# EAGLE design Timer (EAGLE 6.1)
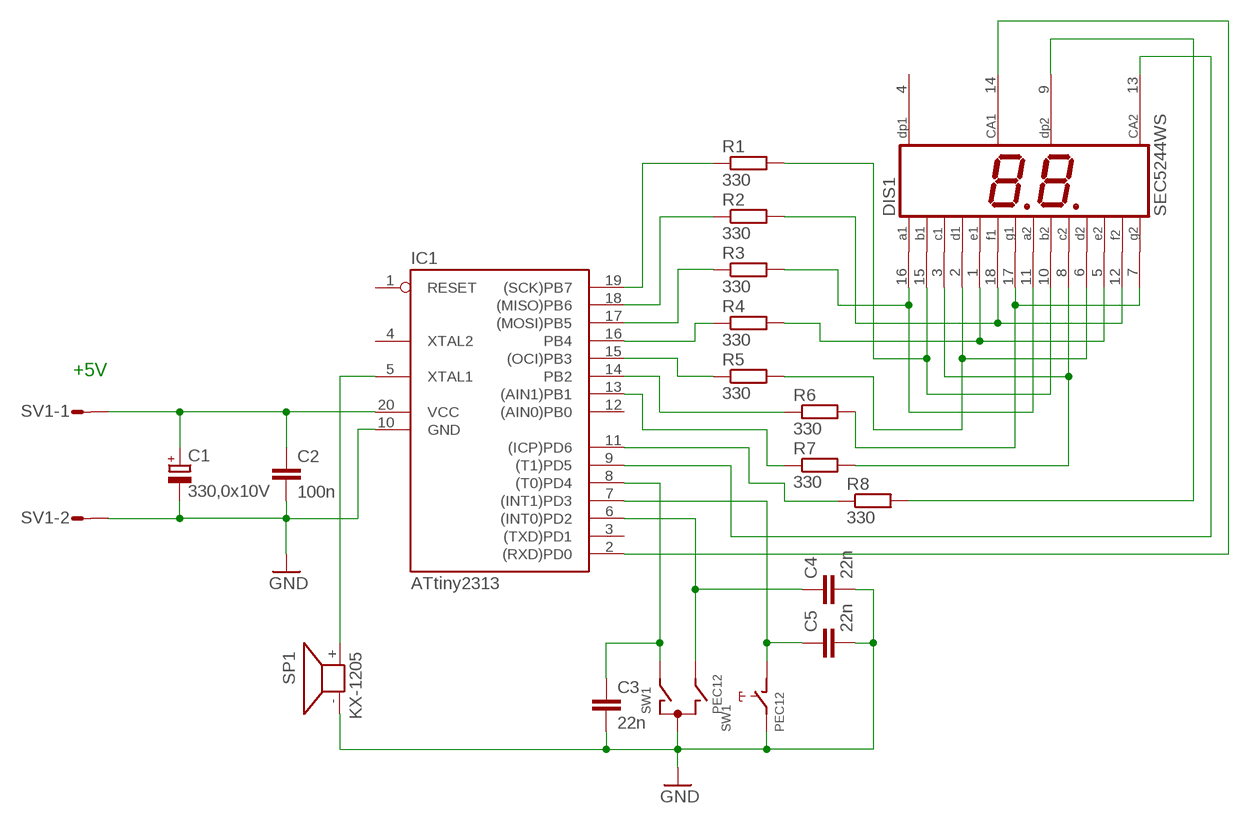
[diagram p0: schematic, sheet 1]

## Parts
C1  330,0x10V  CPOL-EU085CS-1AR  [085CS_1AR]
C2  100n  C-EUC1206  [C1206]
C3  22n  C-EUC1206  [C1206]
C4  22n  C-EUC1206  [C1206]
C5  22n  C-EUC1206  [C1206]
DIS1  SEC5244WS  HD-K121  [HDSP-R]
IC1  ATtiny2313  AT90S2313P  [DIL20]
R1  330  R-EU_R1206  [R1206]
R2  330  R-EU_R1206  [R1206]
R3  330  R-EU_R1206  [R1206]
R4  330  R-EU_R1206  [R1206]
R5  330  R-EU_R1206  [R1206]
R6  330  R-EU_R1206  [R1206]
R7  330  R-EU_R1206  [R1206]
R8  330  R-EU_R1206  [R1206]
SP1  KX-1205  KSS1201  [KSS1201]
SV1  S02P  [S02P]
SW1  PEC12  EC12E_SW  [ALPS_EC12E_SW]

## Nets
GND: C1.- C2.2 C3.2 C4.2 C5.2 IC1.10(GND) SP1.- SV1.2 SW1.C SW1.E
N$1: C1.+ C2.1 IC1.20(VCC) SV1.1
N$2: IC1.14(PB2) R6.1
N$3: IC1.15((OCI)PB3) R5.1
N$4: IC1.16(PB4) R4.1
N$5: IC1.17((MOSI)PB5) R3.1
N$6: IC1.18((MISO)PB6) R2.1
N$7: IC1.19((SCK)PB7) R1.1
N$8: IC1.13((AIN1)PB1) R7.1
N$9: IC1.11((ICP)PD6) R8.1
N$11: DIS1.13(CA2) IC1.9((T1)PD5)
N$12: DIS1.10(B2) DIS1.15(B1) R1.2
N$13: DIS1.9(DP2) R8.2
N$14: DIS1.3(C1) DIS1.8(C2) R7.2
N$15: DIS1.2(D1) DIS1.6(D2) R5.2
N$16: DIS1.14(CA1) IC1.2((RXD)PD0)
N$17: DIS1.12(F2) DIS1.18(F1) R2.2
N$18: DIS1.7(G2) DIS1.17(G1) R6.2
N$19: IC1.5(XTAL1) SP1.+
N$20: DIS1.11(A2) DIS1.16(A1) R3.2
N$21: DIS1.1(E1) DIS1.5(E2) R4.2
N$26: C5.1 IC1.7((INT1)PD3) SW1.D
N$28: C3.1 IC1.8((T0)PD4) SW1.A
N$29: C4.1 IC1.6((INT0)PD2) SW1.B
Unconnected: DIS1.4(DP1) IC1.1(RESET) IC1.3((TXD)PD1) IC1.4(XTAL2) IC1.12((AIN0)PB0) SW1.GND1(G) SW1.GND2(G)

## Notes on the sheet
- +5V

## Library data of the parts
C1 = resistor:CPOL-EU: POLARIZED CAPACITOR, European symbol
C2-C5 = resistor:C-EU: CAPACITOR, European symbol
DIS1 = display-hp:HD-K121: LED DISPLAY 2 x 1 character 7 segment, decimal points right; OC_FARNELL: unknown; OC_NEWARK: unknown
IC1 = atmel:AT90S2313: MICROCONTROLLER 2 Kbytes FLASH 128 bytes SRAM 128 bytes EEPROM UART; OC_FARNELL: unknown; OC_NEWARK: unknown
R1-R8 = resistor:R-EU_: RESISTOR, European symbol
SP1 = buzzer:KSS1201: SPEAKER; OC_FARNELL: unknown; OC_NEWARK: unknown
SV1 = con-amp-mt:S02P: AMP MT CONNECTOR; OC_FARNELL: unknown; OC_NEWARK: unknown
SW1 = switch-alps:EC12E_SW: ALPS rotary Encoder EC12E series with switch; MPN: EC12E2424407; OC_FARNELL: 1520813; OC_NEWARK: 74M1068

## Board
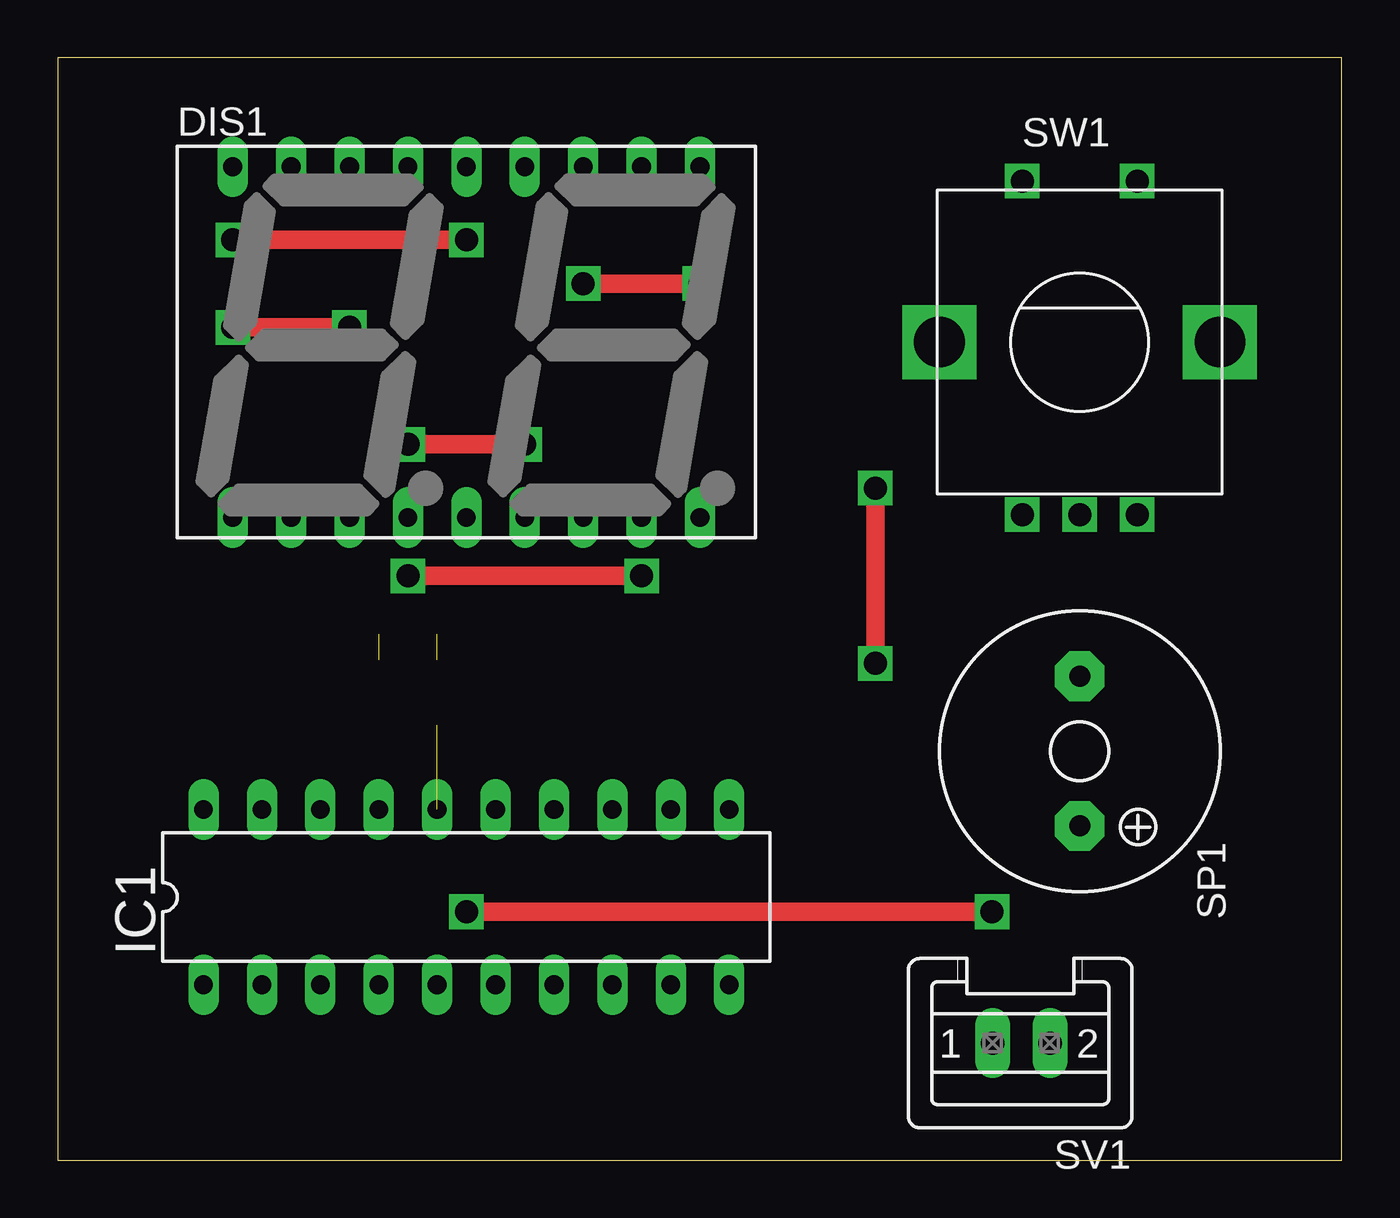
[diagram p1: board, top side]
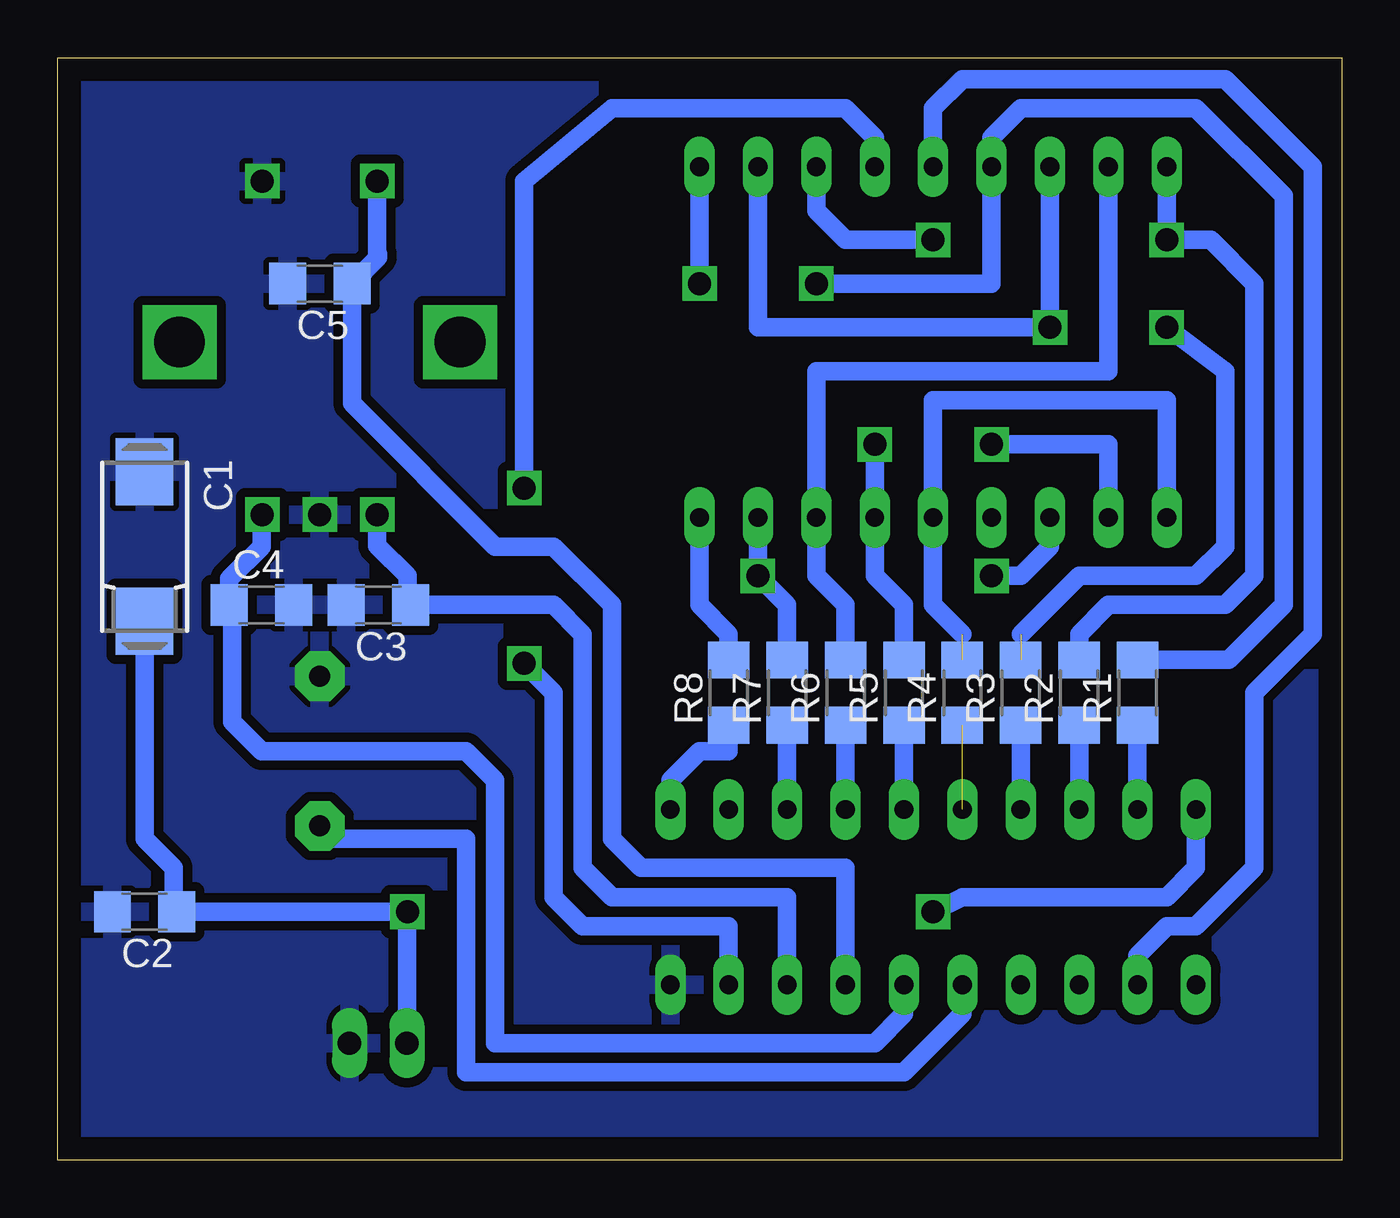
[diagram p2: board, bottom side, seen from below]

Size 55.86 x 47.93 mm. Coordinates in mm from the lower left corner, seen from the top.
Outline: 0,0 55.86,0 55.86,47.93 0,47.93 0,0
Copper layers (1*16): Top 0.035mm / dielectric 1.5mm / Bottom 0.035mm
Design rules "default": minimum track width 10mil, minimum drill 24mil, track to track 8mil, track to pad 8mil, pad to pad 8mil, via to via 8mil, smd to smd 8mil, copper to edge 40mil, drill to drill 8mil, minimum pad ring 10mil, minimum via ring 8mil, stop-mask expansion 4mil, vias tented up to drill 0mil, thermal gap 10mil

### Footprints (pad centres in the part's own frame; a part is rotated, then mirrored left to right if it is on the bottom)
085CS_1AR = smd 2.9 x 2.5: + 3.25,0; - -3.25,0
C1206 = smd 1.6 x 1.8: 1 -1.4,0; 2 1.4,0
HDSP-R = drill 0.813 long: 1 -10.16,-7.62; 2 -7.62,-7.62; 3 -5.08,-7.62; 4 -2.54,-7.62; 5 0,-7.62; 6 2.54,-7.62; 7 5.08,-7.62; 8 7.62,-7.62; 9 10.16,-7.62; 10 10.16,7.62; 11 7.62,7.62; 12 5.08,7.62; 13 2.54,7.62; 14 0,7.62; 15 -2.54,7.62; 16 -5.08,7.62; 17 -7.62,7.62; 18 -10.16,7.62
DIL20 = drill 0.813 long: 1 -11.43,-3.81; 2 -8.89,-3.81; 3 -6.35,-3.81; 4 -3.81,-3.81; 5 -1.27,-3.81; 6 1.27,-3.81; 7 3.81,-3.81; 8 6.35,-3.81; 9 8.89,-3.81; 10 11.43,-3.81; 11 11.43,3.81; 12 8.89,3.81; 13 6.35,3.81; 14 3.81,3.81; 15 1.27,3.81; 16 -1.27,3.81; 17 -3.81,3.81; 18 -6.35,3.81; 19 -8.89,3.81; 20 -11.43,3.81
R1206 = smd 1.6 x 1.803: 1 -1.422,0; 2 1.422,0
KSS1201 = drill 0.914 pad 2.159 octagon: + 3.251,0; - -3.251,0
S02P = drill 1.016 long: 1 1.25,0; 2 -1.25,0
ALPS_EC12E_SW = drill 1 square: A -2.5,-7.5; B 2.5,-7.5; C 0,-7.5; D -2.5,7; E 2.5,7 | drill 2.2 square: GND1 -6.1,0; GND2 6.1,0

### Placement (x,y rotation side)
C1  52.07,26.67 270 bottom
C2  52.07,10.79 180 bottom
C3  41.91,24.13 180 bottom
C4  46.99,24.13 0 bottom
C5  44.45,38.1 180 bottom
DIS1  17.78,35.56 0 top
IC1  17.78,11.43 0 top
R1  8.89,20.32 90 bottom
R2  11.43,20.32 90 bottom
R3  13.97,20.32 90 bottom
R4  16.51,20.32 90 bottom
R5  19.05,20.32 90 bottom
R6  21.59,20.32 90 bottom
R7  24.13,20.32 90 bottom
R8  26.67,20.32 90 bottom
SP1  44.45,17.78 270 top
SV1  41.91,5.08 180 top
SW1  44.45,35.56 0 top

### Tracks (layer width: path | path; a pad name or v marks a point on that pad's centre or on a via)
GND
  Bottom 0.813: SW1.C 44.45,27.94
  pour Bottom (isolate 0.406): 0,48.26 55.88,48.26 55.88,0 0,0
N$1  (via drill 1)
  Top 0.813: v17.78,10.79 v40.64,10.79
  Bottom 0.813: IC1.20 6.35,12.7 7.62,11.43 16.51,11.43 v17.78,10.79 | SV1.1 40.66,10.14 v40.64,10.79 C2.1 50.8,11.56 50.8,12.7 52.07,13.97 C1.+
N$2
  Bottom 0.813: IC1.14 R6.1
N$3
  Bottom 0.813: IC1.15 R5.1
N$4  (1 unrouted)
N$5
  Bottom 0.813: IC1.17 R3.1
N$6
  Bottom 0.813: IC1.18 R2.1 IC1.18
N$7
  Bottom 0.813: IC1.19 R1.1
N$8
  Bottom 0.813: IC1.13 R7.1
N$9
  Bottom 0.813: R8.1 26.67,17.78 27.94,17.78 29.21,16.51 IC1.11
N$11  (via drill 1)
  Top 0.813: v35.56,21.59 v35.56,29.21
  Bottom 0.813: IC1.9 26.67,10.16 33.02,10.16 34.29,11.43 34.29,20.32 v35.56,21.59 | DIS1.13 20.32,44.45 21.59,45.72 31.75,45.72 35.56,42.55 v35.56,29.21
N$12  (via drill 1)
  Top 0.813: v22.86,38.1 v27.94,38.1
  Bottom 0.813: v27.94,38.1 DIS1.10 | R1.2 4.93,21.74 2.54,24.13 2.54,41.91 6.35,45.72 13.97,45.72 15.24,44.45 DIS1.15 15.24,38.1 v22.86,38.1
N$13
  Bottom 0.813: R8.2 26.67,22.86 27.94,24.13 DIS1.9
N$14  (via drill 1)
  Top 0.813: v15.24,25.4 v25.4,25.4
  Bottom 0.813: DIS1.8 v25.4,25.4 24.13,24.13 R7.2 | DIS1.3 12.7,26.67 13.97,25.4 v15.24,25.4
N$15  (via drill 1)
  Top 0.813: v20.32,31.11 v15.24,31.11
  Bottom 0.813: v20.32,31.11 DIS1.6 20.32,25.4 19.05,24.13 R5.2 | DIS1.2 10.16,31.11 v15.24,31.11
N$16
  Bottom 0.813: IC1.2 8.89,8.89 7.62,10.16 6.35,10.16 3.81,12.7 3.81,20.32 1.27,22.86 1.27,43.18 5.08,46.99 16.51,46.99 17.78,45.72 DIS1.14
N$17  (via drill 1)
  Top 0.813: v7.62,40.01 v17.78,40.01
  Bottom 0.813: DIS1.18 v7.62,40.01 5.71,40.01 3.81,38.1 3.81,25.4 5.08,24.13 10.16,24.13 11.43,22.86 R2.2 | DIS1.12 22.86,41.27 21.59,40.01 v17.78,40.01
N$18
  Bottom 0.813: DIS1.17 10.16,34.29 22.86,34.29 DIS1.7 22.86,25.4 21.59,24.13 R6.2
N$19
  Bottom 0.813: IC1.5 16.51,6.35 19.05,3.81 38.1,3.81 38.1,13.97 43.89,13.97 SP1.+
N$20  (via drill 1)  (1 unrouted)
  Top 0.813: v7.62,36.2 v12.7,36.2
  Bottom 0.813: DIS1.16 v12.7,36.2 25.4,36.2 DIS1.11 | 13.97,22.86 11.43,25.4 6.35,25.4 5.08,26.67 5.08,34.29 v7.62,36.2
N$21  (1 unrouted)
  Bottom 0.813: DIS1.1 7.62,33.02 17.78,33.02 DIS1.5 17.78,24.13 16.51,22.86
N$26
  Bottom 0.813: SW1.D 41.95,39.41 41.91,39.37 41.91,39.24 C5.1 43.05,32.89 36.83,26.67 34.29,26.67 31.75,24.13 31.75,13.97 30.48,12.7 21.59,12.7 IC1.7
N$28
  Bottom 0.813: SW1.A 41.95,26.71 40.64,25.4 40.64,24.26 C3.1 | C3.1 40.64,24 | IC1.8 24.13,11.43 31.75,11.43 33.02,12.7 33.02,22.86 34.29,24.13 C3.1
N$29
  Bottom 0.813: SW1.B 46.99,28.02 46.99,26.67 48.39,25.27 C4.1 48.26,24 48.26,19.05 46.99,17.78 38.1,17.78 36.83,16.51 36.83,5.08 20.32,5.08 19.05,6.35 IC1.6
